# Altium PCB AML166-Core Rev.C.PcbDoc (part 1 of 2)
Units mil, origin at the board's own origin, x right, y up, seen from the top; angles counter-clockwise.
Board outline 3307.09 x 2047.24 mil, 4 copper layers (Top Layer, L2, L3, Bottom Layer), stack 30.634 mil thick; 138 components, 74 nets, 392 pads, 430 vias.
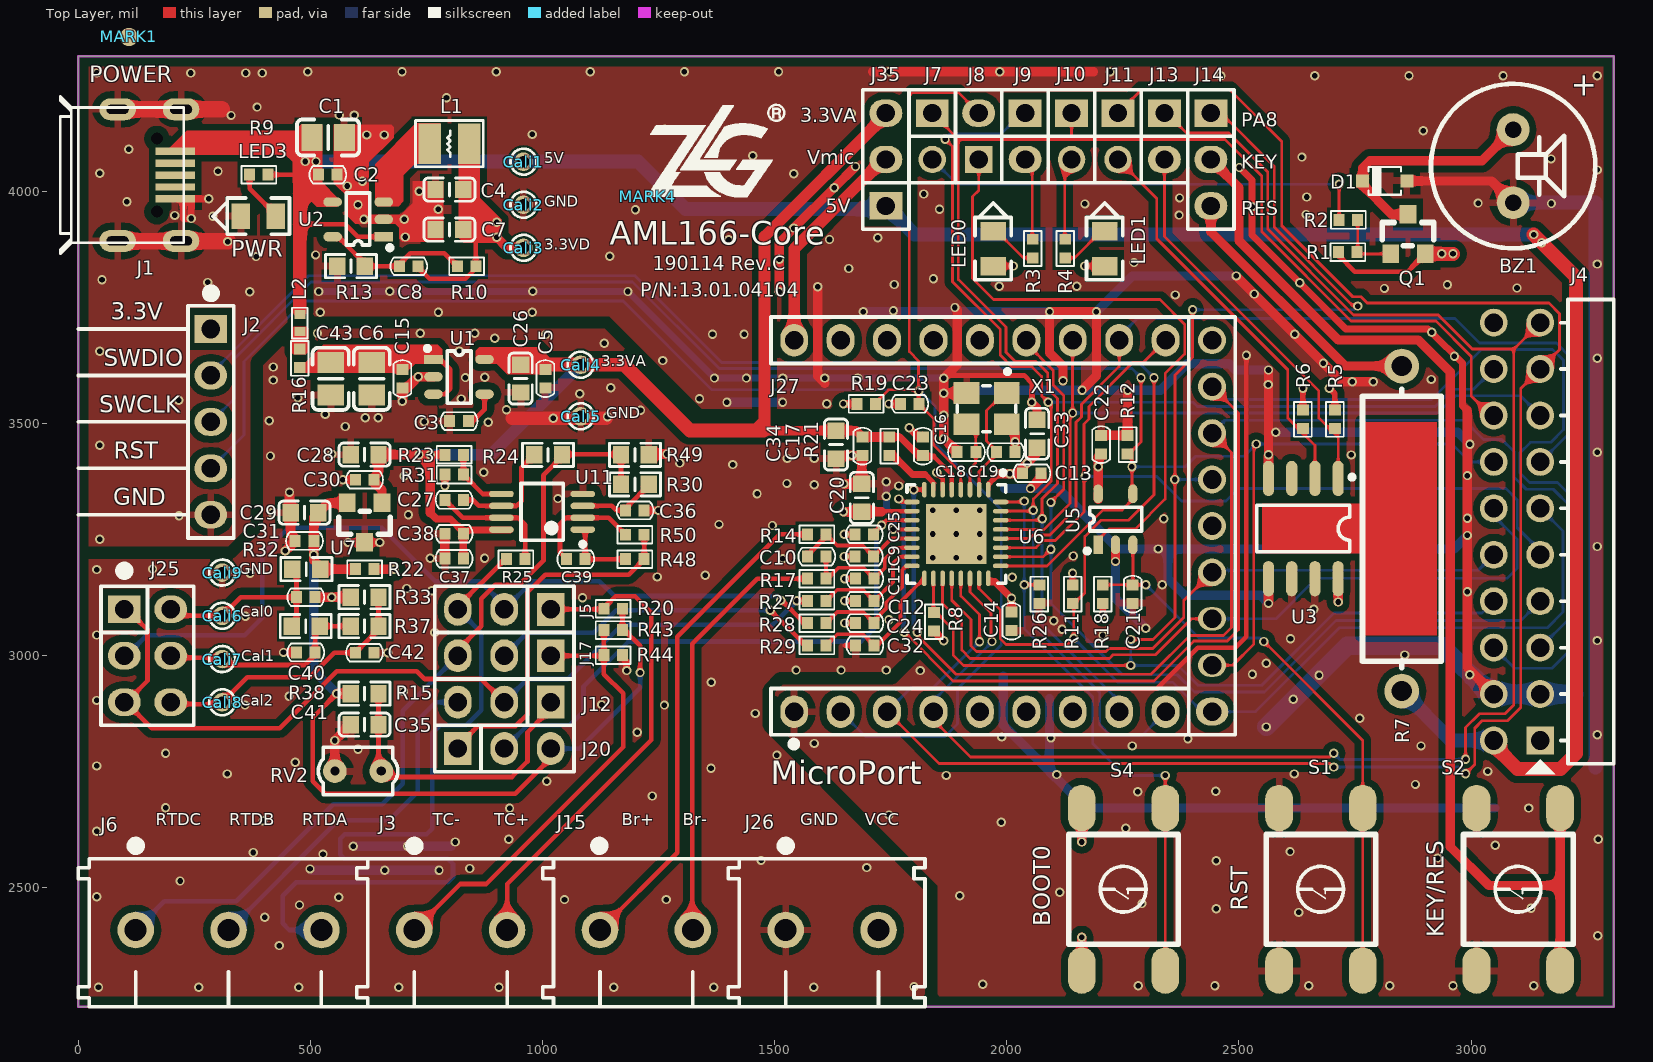
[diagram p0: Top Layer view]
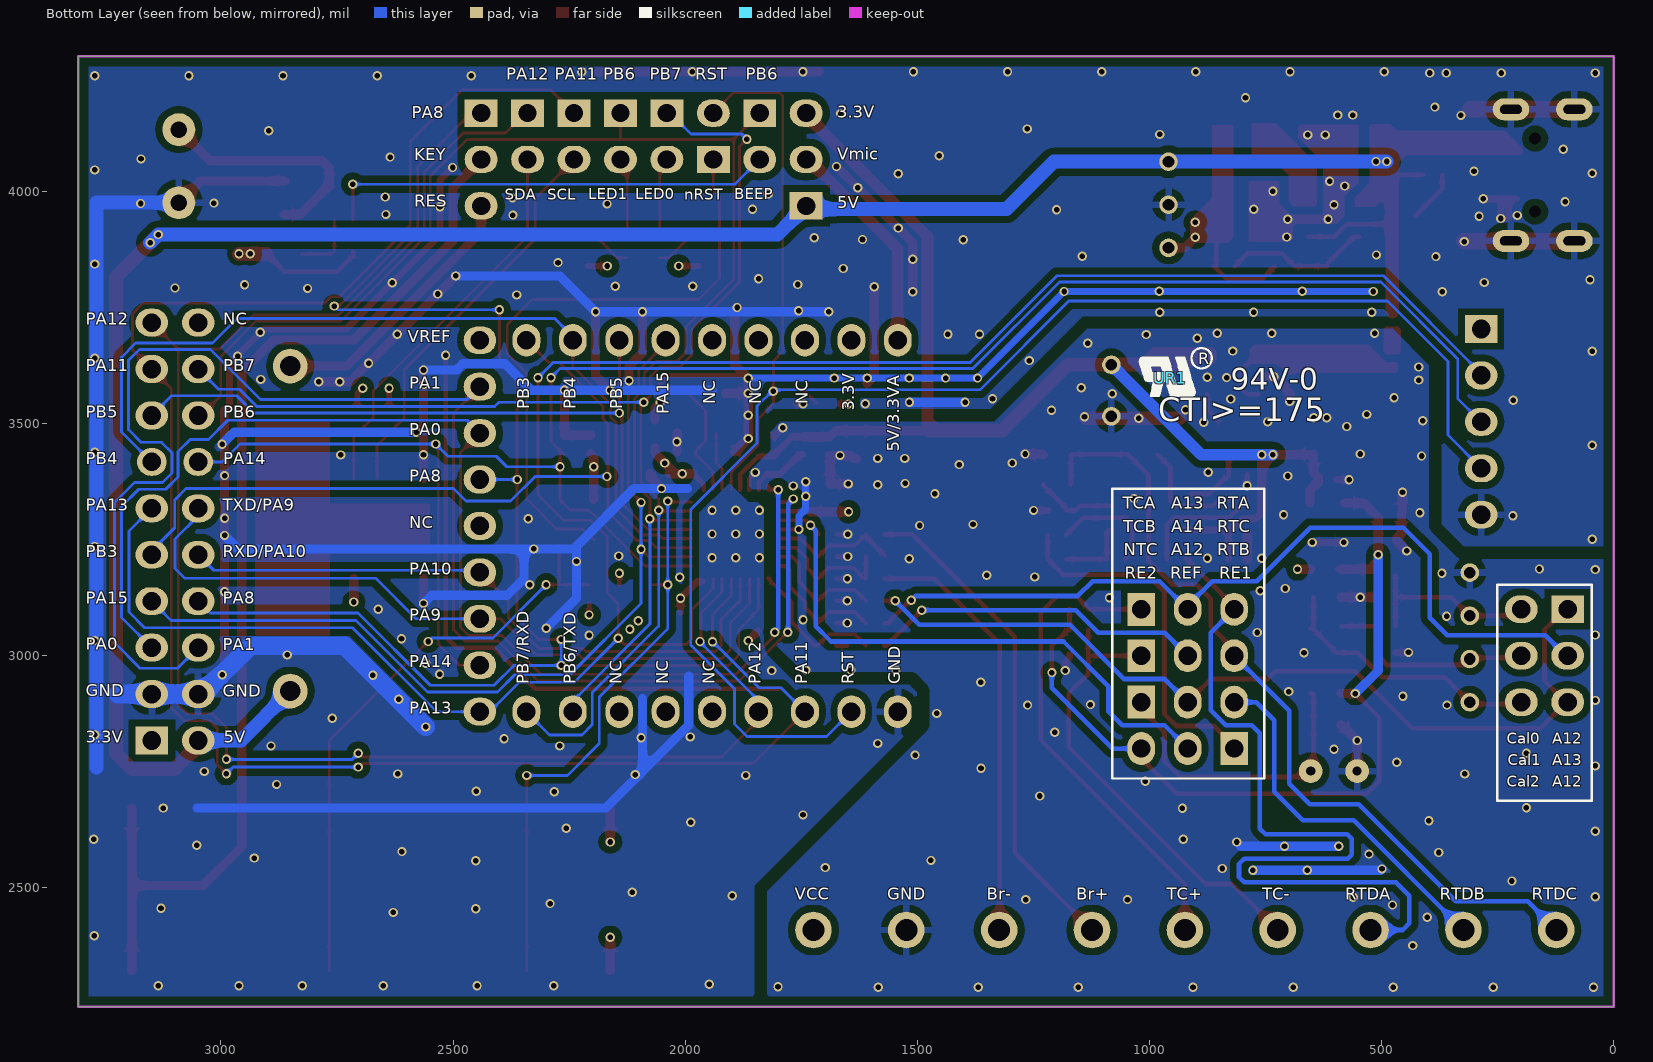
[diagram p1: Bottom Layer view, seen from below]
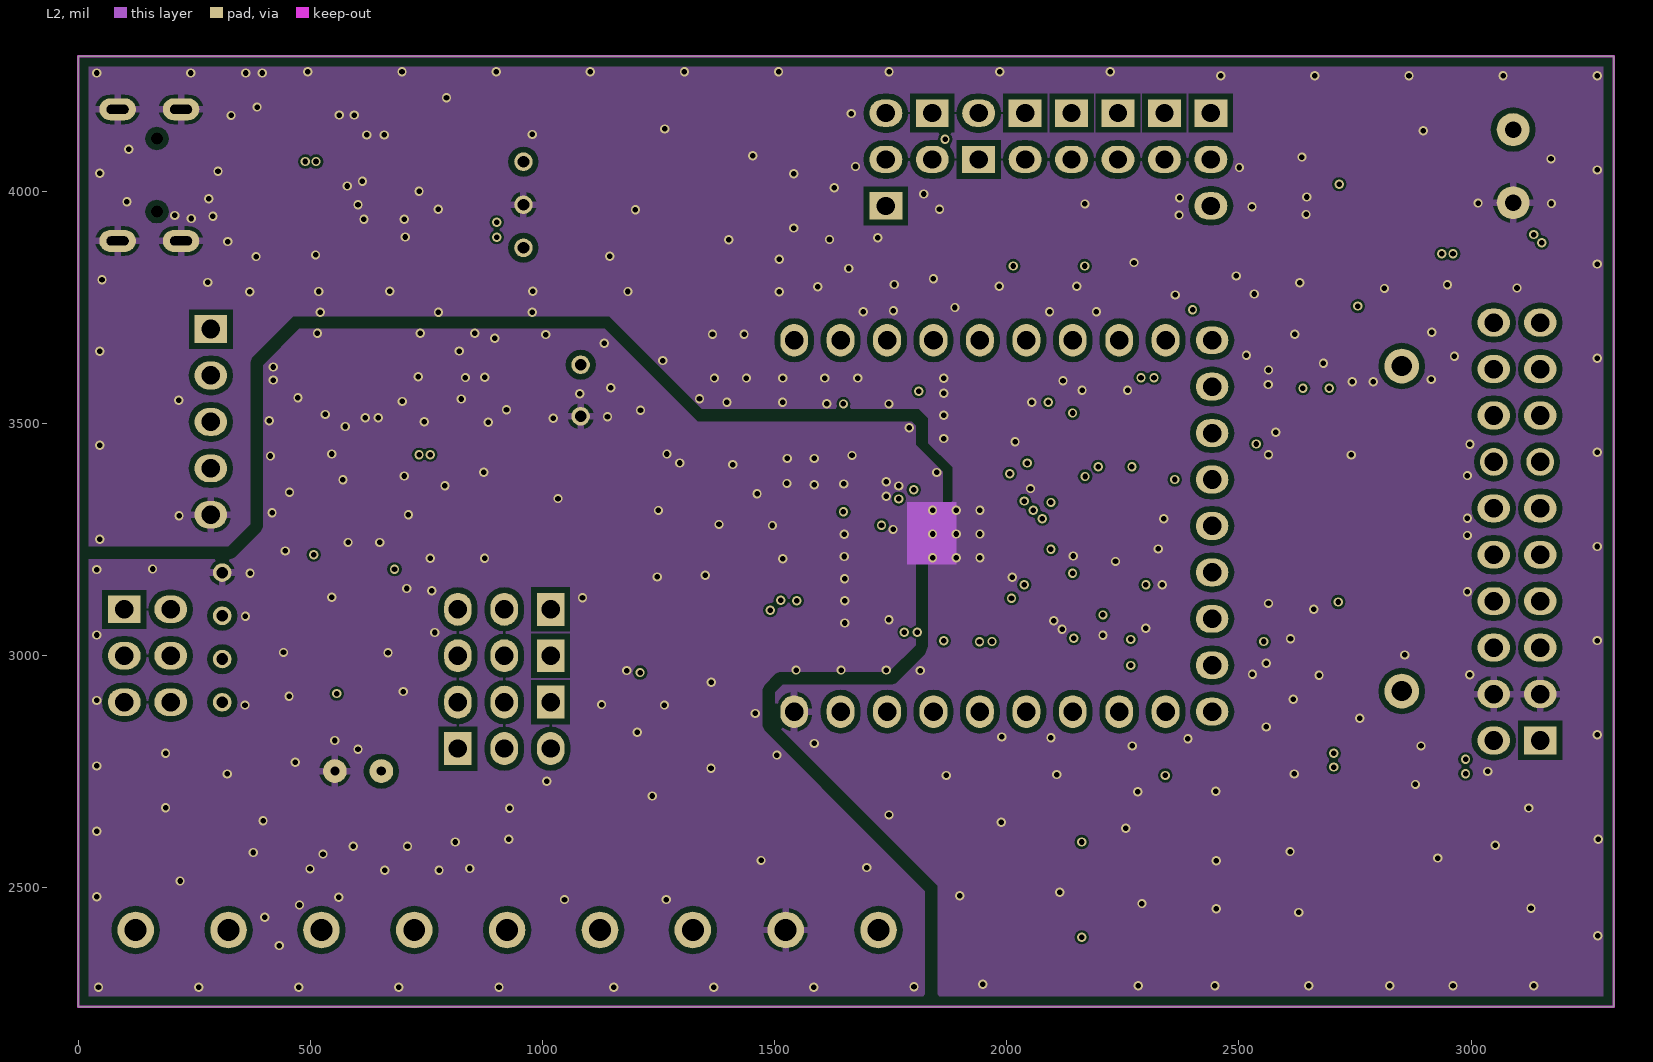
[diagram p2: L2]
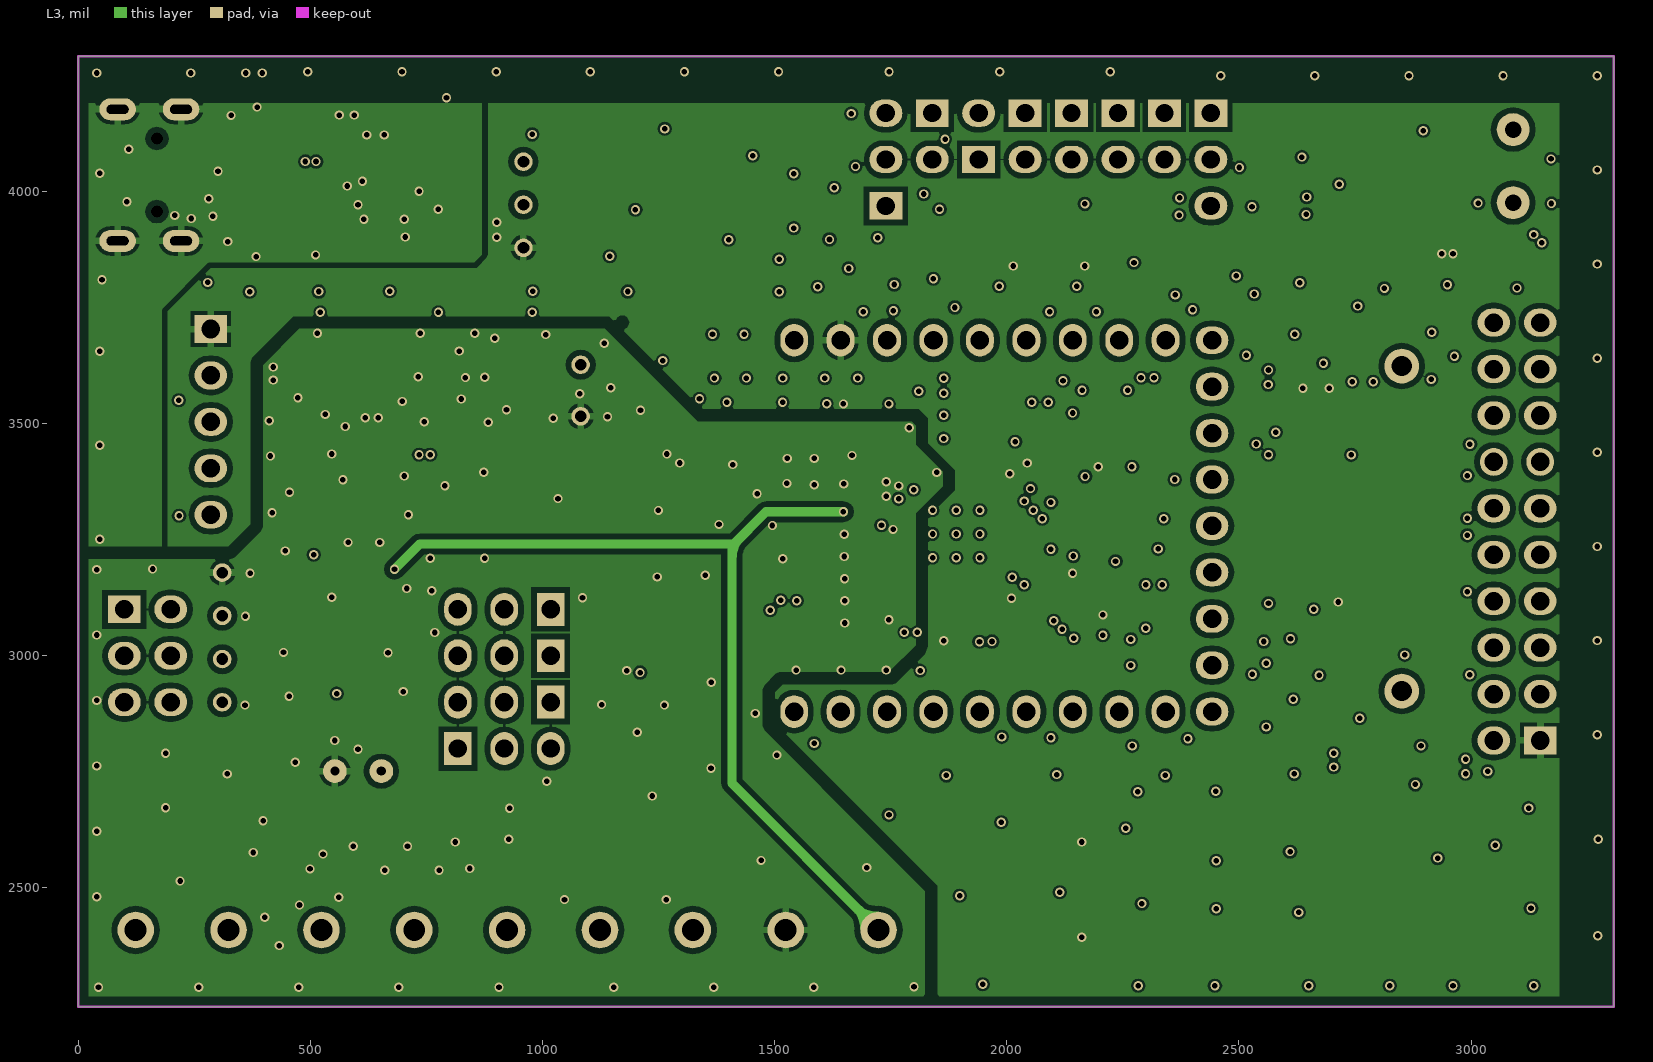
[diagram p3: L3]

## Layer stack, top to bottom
Top Layer: signal copper 1.4
Dielectric: core 10, FR-4, Dk 4.2
L2: signal copper 1.417
Dielectric: prepreg 5, Dk 4.2
L3: signal copper 1.417
Dielectric: core 10, Dk 4.2
Bottom Layer: signal copper 1.4

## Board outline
0,2244.09 3307.09,2244.09 3307.09,4291.34 0,4291.34

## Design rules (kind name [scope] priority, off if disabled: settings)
Clearance Clearance_Keepout [OnLayer('Keep-Out Layer')] p1: gap=20
Clearance Clearance_TP [HasFootprint('PAD-40') vs HasFootprint('PAD-40')] p2: gap=50
Clearance Clearance_Manual [OnLayer('Bottom Layer') and IsSMTPin vs IsPadHoleValid>  (  HasFootprint('PAD-35/50') or   HasFootprint('HOLE-3.2') or  HasFootprint('HOLE-3.2 - Screw') or   HasFootprint('HOLE4.22-SMT') or   HasFootprint('Mou Hole-300D450W310H-SMD') or  HasFootprint('AW6748') or  HasFootprint('IDCS80P500W-20X2-F')  )] p3: gap=50
Clearance Clearance_Via2Via [IsVia vs IsVia] p4: gap=6
Clearance Clearance_Surface [InLayerClass('Component Layers')] p5: gap=5
Clearance Clearance_Inner [inpoly] p6: gap=5
Clearance [All] p7: gap=6
DiffPairsRouting [All] p1: maxlimit=6 minlimit=6 mostfreqgap=6 maxuncoupledlength=500
HoleSize [All] p1: absolutevalues=TRUE maxlimit=1000 minlimit=1 maxpercent=80.000 minpercent=20.000
MinimumSolderMaskSliver [All] p1: minsoldermaskwidth=4
PlaneClearance PlaneClearance_Full [IsVia] p1: clearance=9
PlaneClearance [All] p2: clearance=22
PlaneConnect PlaneConnect_Full [IsVia] p1: planeconnectstyle=Direct reliefexpansion=20 reliefentries=4 reliefconductorwidth=10 reliefairgap=10
PlaneConnect [All] p2: planeconnectstyle=Relief reliefexpansion=16 reliefentries=4 reliefconductorwidth=15 reliefairgap=6
PolygonConnect PolygonConnect_SMDHole [HasFootprint('Mou Hole-300D450W310H-SMD') or HasFootprint('Mou Hole-373D600H-SMD')] p1: connectstyle=Relief reliefconductorwidth=80 reliefentries=4 polygonreliefangle="45 Angle"
PolygonConnect PolygonConnect_Full [IsVia or   HasFootprint('PAD-40') or   HasFootprint('PAD-35/50') or  HasFootprint('HOLE-3.2') or   HasFootprint('HOLE-3.2 - Screw')] p2: connectstyle=Direct reliefconductorwidth=10 reliefentries=4 polygonreliefangle="90 Angle"
PolygonConnect PolygonConnect_Surface [OnLayer('Top Layer')  or  OnLayer('Bottom Layer')] p3: connectstyle=Relief reliefconductorwidth=15 reliefentries=4 polygonreliefangle="90 Angle"
PolygonConnect PolygonConnect_Inner [All] p4: connectstyle=Relief reliefconductorwidth=15 reliefentries=4 polygonreliefangle="90 Angle"
RoutingVias [All] p1: holewidth=12 width=20 viastyle="Through Hole" minholewidth=12 minwidth=20 maxholewidth=12 maxwidth=20
SilkToSilkClearance [All] p1: silktosilkclearance=2
SilkscreenOverComponentPads SilkToSolderMaskClearance [IsPad] p1: minsilkscreentomaskgap=2
SolderMaskExpansion [All] p1: expansion=4
Width [All] p1: maxlimit=100 minlimit=5.5 preferedwidth=5.5
21 further rules are at their usual default settings.

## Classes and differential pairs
component class U_09: C21 C22 R18 S1 U5
component class U_08: C9 C10 C11 C12 C13 C14 C16 C17 C18 C19 C20 C23 C24 C25 C27 C28 C30 C31 C32 C33 C34 C35 C36 C37 C38 C39 C40 C41 C42 Cali6 Cali7 Cali8 Cali9 J2 J5 J8 J12 J17 J20 J25 R11 R12 R14 R15 R17 R19 R20 R21 R22 R23 R24 R25 R26 R27 R28 R29 R30 R31 R32 R33 R37 R38 R43 R44 R48 R49 R50 RV2 S4 U6 U7 U11 X1
component class U_07: J1
component class U_05: J4
component class U_04: J27 J35
component class U_03: BZ1 D1 J7 J9 J10 J11 J13 J14 LED0 LED1 Q1 R1 R2 R3 R4 R5 R6 R7 R8 S2 U3
component class U_02B: C1 C2 C3 C4 C5 C6 C7 C8 C15 C26 C43 Cali1 Cali2 Cali3 Cali4 Cali5 L1 L2 LED3 R9 R10 R13 R16 U1 U2
component class 01.mian: J3 J6 J15 J26 MARK1 MARK2 MARK3 MARK4 UR1

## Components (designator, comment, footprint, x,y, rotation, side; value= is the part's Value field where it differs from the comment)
BZ1 "BUZZER2" BUZZ-4/9 3090.55,4054.8 r270 top locked
C1 "10μF,10V" 0805C 538,4116.47 r0 top
C2 "0.1μF,±10%" 0402C 537.5,4036.37 r0 top
C3 "0.01μF,±10%" 0402C 820,3505.71 r180 top
C4 "10μF,6.3V" 0603C 799.31,4004.37 r180 top
C5 "0.1μF,±10%" 0402C 1006,3597.2 r270 top
C6 "10μF,10V" 0805C 632,3596.7 r270 top
C7 "10μF,6.3V" 0603C 799.31,3918.18 r180 top
C8 "18pF" 0402C 711.81,3839.18 r180 top
C9 "0.1μF" 0402C 1693.09,3213.93 r180 top
C10 "1μF,±10%" 0402C 1590.69,3213.93 r0 top
C11 "0.1μF" 0402C 1694.09,3166.18 r180 top
C12 "0.1μF" 0402C 1694.24,3118.43 r180 top
C13 "0.1μF" 0402C 2054,3393.34 r0 top
C14 "0.1μF" 0402C 2010,3074.49 r270 top
C15 "0.1μF,±10%" 0402C 698,3597.2 r270 top
C16 "0.1μF" 0402C 1819.03,3451.65 r90 top
C17 "0.1μF" 0402C 1689,3451.65 r270 top
C18 "12pF,±5%" 0402C 1913.09,3438.92 r0 top
C19 "12pF,±5%" 0402C 1997.73,3438.92 r0 top
C20 "10μF" 0603C 1687.49,3340.3 r90 top
C21 "0.1μF,±10%" 0402C 2271,3133.02 r270 top
C22 "0.1μF,±10%" 0402C 2203.09,3455.02 r270 top
C23 "0.1μF,±10%" 0402C 1791,3542.53 r180 top
C24 "0.1μF" 0402C 1694.24,3070.68 r180 top
C25 "1μF" 0402C 1693.09,3261.68 r0 top
C26 "10μF,6.3V" 0603C 952.59,3597.2 r270 top
C27 "22pF,±5%" 0402C 809.37,3335.91 r180 top
C28 "10μF" 0603C 616.57,3433.39 r0 top
C29 "10μF,6.3V" 0603C 487.16,3308.46 r0 top
C30 "0.1μF" 0402C 616.57,3379.39 r180 top
C31 "0.1μF" 0402C 487.16,3247.37 r180 top
C32 "0.1μF" 0402C 1694.24,3022.34 r180 top
C33 "10μF,6.3V" 0603C 2065.09,3478.34 r270 top
C34 "10μF,6.3V" 0603C 1632,3455 r90 top
C35 "10μF" 0603C 616.57,2851.71 r0 top
C36 "1μF,±10%" 0402C 1198.94,3313.27 r0 top
C37 "4.7μF" 0402C 809.37,3209.27 r180 top
C38 "0.1μF" 0402C 809.37,3263.08 r180 top
C39 "0.01μF,±10%" 0402C 1071.76,3208.27 r0 top
C40 "1μF,±10%" 0402C 490,3126.37 r180 top
C41 "1μF,±10%" 0402C 490,3007.37 r0 top
C42 "1μF,±10%" 0402C 616.57,3006.73 r180 top
C43 "10μF,10V" 0805C 543.62,3596.7 r270 top
Cali1 "5V" PAD-25/40 958.81,4064.37 r90 top
Cali2 "GND" PAD-25/40 958.81,3971.59 r90 top
Cali3 "3.3V" PAD-25/40 958.81,3878.81 r0 top
Cali4 "5V" PAD-25/40 1082,3627 r90 top
Cali5 "GND" PAD-25/40 1082,3516 r90 top
Cali6 "TEST1" PAD-25/40 309.87,3086.23 r180 top
Cali7 "TEST2" PAD-25/40 309.87,2993.11 r180 top
Cali8 "TEST3" PAD-25/40 309.87,2900 r180 top
Cali9 "TEST0" PAD-25/40 309.87,3179.34 r180 top
D1 "DIODE1" SOD-323 2814.09,4022.84 r180 top
J1 "A01SB141B1-261,MicroUSB插座" MICROUSB-5S 0,4035.43 r270 top locked
J2 "SWDIO" SIP-5-2.54-6.0-R90 285.43,3503.94 r270 top locked
J3 "Value" CON508P810W130D15S-2DIP 823.62,2403.54 r0 top locked
J4 "HEADER 10X2" IDC-20-2.54-R90 3098.82,3267.72 r90 top locked
J5 "CON3" SIP-3-2.54 917.52,3100.24 r180 top
J6 "DG127-5.08" CON508P1524L810W110D15S-3DIP 323.62,2403.54 r0 top locked
J7 "BEEP" SIP-2-2.54#1 1839.37,4119.09 r270 top locked
J8 "nRST" SIP-2-2.54#2 1939.37,4119.09 r90 top locked
J9 "LED0" SIP-2-2.54#3 2039.37,4119.09 r270 top locked
J10 "LED1" SIP-2-2.54#1 2139.37,4119.09 r270 top locked
J11 "SCL" SIP-2-2.54#1 2239.37,4119.09 r270 top locked
J12 "CON3" SIP-3-2.54 917.52,2900.24 r180 top locked
J13 "SDA" SIP-2-2.54#3 2339.37,4119.09 r270 top locked
J14 "KEY" SIP-3-2.54 2439.37,4069.09 r270 top locked
J15 "Value" CON508P810W130D15S-2DIP 1223.62,2403.54 r0 top locked
J17 "CON3" SIP-3-2.54 917.52,3000.24 r180 top
J20 "CON3" SIP-3-2.54 917.52,2800.24 r0 top locked
J25 "HEADER 3X2" IDC-6-2.54 149,3000.24 r270 top
J26 "Value" CON508P810W130D15S-2DIP 1623.62,2403.54 r0 top locked
J27 "3X7Inter" "SIP-27 2.54C" 1991.98,3279.79 r90 top locked
J35 "Vol_Sel" SIP-3-2.54 1739.37,4069.09 r90 top locked
L1 "MPH252012C2R2MT,2.2μH" INDC2520X10N 799.31,4103.37 r0 top
L2 "BM02Y190S40R" 0402RL 477,3716.89 r90 top
LED0 "LED1" LED-0805 1970.63,3877.29 r90 top
LED1 "LED1" LED-0805 2210.71,3877.29 r90 top
LED3 "LED1" LED-0805 388,3947 r180 top
MARK1 "MARKER" MARKER-C-1.0M 109,4333 r90 top
MARK2 "MARKER" MARKER-C-1.0M 105,155 r90 top
MARK3 "MARKER" MARKER-C-1.0M 6467,156 r90 top
MARK4 "ZLG" ZLG0.7 1226.51,3989.09 r0 top
Q1 "PNP-1" SOT-23 2864.09,3908.34 r90 top
R1 "RTT02103JTH,10K" 0402R 2734.5,3869.82 r180 top
R2 "1.5K,±1%" 0402R 2735.69,3938.82 r0 top
R3 "1.5K,±1%" 0402R 2055.71,3877.29 r90 top
R4 "1.5K,±1%" 0402R 2125.71,3877.29 r90 top
R5 "RTT02103JTH,10K" 0402R 2706.72,3509.34 r90 top
R6 "RTT02103JTH,10K" 0402R 2637.72,3509.34 r90 top
R7 "20Ω,±5%" RESAD1778W80L1450D430P 2850.63,3274.09 r90 top locked
R8 "RTT02472JTH,4.7K" 0402R 1843,3073.37 r90 top
R9 "1.5K,±1%" 0402R 389,4036.37 r0 top
R10 "680K,1%" 0402R 836.31,3839.18 r0 top
R11 "RTT02103JTH,10K" 0402R 2142,3133.02 r90 top
R12 "RTT02103JTH,10K" 0402R 2260,3455.02 r270 top
R13 "150KΩ" 0603R 587.31,3839.18 r0 top
R14 "100Ω,±1%" 0402R 1590.69,3261.68 r0 top
R15 "10KΩ,1/16W" 0603R 616.57,2918.71 r0 top
R16 "10Ω,±0.5%" 0402R 477,3640.62 r270 top
R17 "100Ω,±1%" 0402R 1590.69,3166.18 r0 top
R18 "RTT02103JTH,10K" 0402R 2206.5,3133.02 r90 top
R19 "RTT02103JTH,10K" 0402R 1697,3542.53 r0 top
R20 "10M,±5%" 0402R 1152,3101.49 r0 top
R21 "RTT02000JTH,0Ω" 0402R 1746.7,3451.65 r270 top
R22 "RTT02000JTH,0Ω" 0402R 616.57,3186.71 r0 top
R23 "12K,±5%" 0402R 809.37,3432.96 r0 top
R24 "4.7KΩ" 0603R 1011.85,3432.96 r180 top
R25 "100Ω,±1%" 0402R 942.35,3208.27 r180 top
R26 "RTT02103JTH,10K" 0402R 2070,3133.02 r270 top
R27 "100Ω,±1%" 0402R 1590.69,3118.43 r0 top
R28 "100Ω,±1%" 0402R 1590.69,3070.39 r0 top
R29 "100Ω,±1%" 0402R 1590.69,3022.34 r0 top
R30 "47KΩ" 0603R 1198.94,3369.27 r0 top
R31 "20KΩ,±0.5%" 0402R 809.37,3390.44 r0 top
R32 "20KΩ,1/16W" 0603R 491.16,3186.71 r0 top
R33 "20KΩ,1/16W" 0603R 616.57,3126.37 r180 top
R37 "499Ω" 0603R 616.57,3064 r180 top
R38 "51Ω,10ppm" 0603R 490,3064 r0 top
R43 "1K,±1%" 0402R 1152,3055.49 r0 top
R44 "1K,±1%" 0402R 1152,3001.49 r0 top
R48 "200Ω,±1%" 0402R 1198.94,3208.27 r0 top
R49 "2KΩ" 0603R 1198.94,3432.96 r180 top
R50 "100Ω,±0.5%" 0402R 1198.94,3260.77 r180 top
RV2 "103AP2" RESRR254W35L380T260H850P 602.57,2751.71 r0 top
S1 "TS0641-0501B,6×6×5.0mm" KEY-6S 2676.52,2497.09 r90 top
S2 "SW-PB4P" KEY-6S 3101.69,2497.09 r90 top
S4 "SW-PB4P" KEY-6S 2251.34,2497.09 r90 top
U1 "CAT6219-330TD" SOT-23-5 820,3601.07 r0 top
U2 "NCP1529ASNT1G" SOT-23-5 602.81,3940.18 r180 top
U3 "LM75B" SOIC127P600X175-8N 2638.63,3274.09 r270 top locked
U5 "CAT823STDI-GT3" SOT-23-5 2234.09,3294.02 r90 top
U6 "ZML166" QFN50P500X500X85-33N 1891.09,3262.51 r270 top
U7 "REF3325AIDBZR" SOT-23 616.57,3286.8 r270 top
U11 "TP5592-VR" SOP65P490X120-8N 998.94,3310.27 r180 top
UR1 "UR" ZY_UR-3X2 955.48,3597.98 r180 bottom
X1 "JYD3A1C7G5-12.5-16.000,16.0000MHz" OSCCC250X320X80-4N 1956.39,3532.24 r180 top

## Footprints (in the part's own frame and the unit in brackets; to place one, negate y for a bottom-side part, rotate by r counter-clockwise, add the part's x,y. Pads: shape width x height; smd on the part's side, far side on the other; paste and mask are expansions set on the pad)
0402C [mm]
  rect 0.6x0.65 smd mask+0.025: 1(-0.508,0) 2(0.508,0)
  silkscreen extent -1.01,-0.48 1.01,0.48, body extent -0.51,-0.23 0.49,0.27, height 0.5
0402R [mm]
  rect 0.6x0.65 smd mask+0.025: 1(-0.508,0) 2(0.508,0)
  silkscreen extent -0.95,-0.48 0.95,0.48, body extent -0.47,-0.25 0.53,0.25, height 0.35
0402RL [mm]
  rect 0.5x0.6 smd mask+0.051: 1(-0.458,0) 2(0.458,0)
  silkscreen extent -0.84,-0.43 0.84,0.43, body extent -0.52,-0.25 0.48,0.25, height 0.35
0603C [mm]
  rect 0.9x0.95 smd: 1(-0.762,0) 2(0.762,0)
  silkscreen extent -1.4,-0.64 1.4,0.64, body extent -0.79,-0.38 0.81,0.42, height 0.3
0603R [mm]
  rect 0.9x0.95 smd: 1(-0.762,0) 2(0.762,0)
  silkscreen extent -1.4,-0.64 1.4,0.64, body extent -0.8,-0.4 0.8,0.4, height 0.3
0805C [mm]
  rect 1.15x1.45 smd: 1(-0.889,0) 2(0.889,0)
  silkscreen extent -1.7,-0.99 1.7,0.99, body extent -1,-0.63 1,0.63, height 0.78
BUZZ-4/9 [mm]
  round 1.8 hole 0.9: 1(-2,0) 2(2,0)
  silkscreen extent -4.5,-4.5 4.5,4.5
CON508P810W130D15S-2DIP [mm]
  round 2 hole 1.2: 1(-2.54,0.15) 2(2.54,0.15)
  silkscreen extent -5.68,-4.05 5.08,5
CON508P1524L810W110D15S-3DIP [mm]
  round 2 hole 1.2: 1(-5.08,0.15) 2(0,0.15) 3(5.08,0.15)
  silkscreen extent -8.22,-4.05 7.62,5
IDC-6-2.54 [mm]
  rect 1.5x1.8 hole 1: 1(-2.54,-1.27)
  oval 1.5x1.8 hole 1: 2(-2.54,1.27) 3(0,-1.27) 4(0,1.27) 5(2.54,-1.27) 6(2.54,1.27)
  silkscreen extent -4.9,-2.54 3.81,2.54, body extent -3.81,-2.54 3.81,2.54, height 7.58
IDC-20-2.54-R90 [mil]
  rect 60x60 / inner rect 60x70 / far side rect 60x70 hole 40: 1(-450,-50)
  round 60 / inner oval 60x70 / far side oval 60x70 hole 40: 2(-450,50) 3(-350,-50) 4(-350,50) 5(-250,-50) 6(-250,50) 7(-150,-50) 8(-150,50) 9(-50,-50) 10(-50,50) 11(50,-50) 12(50,50) 15(250,-50) 16(250,50) 17(350,-50) 18(350,50) 19(450,-50) 20(450,50)
  round 60 / inner round 60 / far side oval 60x64 hole 40: 13(150,-50) 14(150,50)
  silkscreen extent -522,-208 500,-17
INDC2520X10N [mm] "Chip Inductor, 2-Leads, Body 2.50x2.00mm, IPC Medium Density"
  rect 1.23x2.22 smd: 1(-1.085,0) 2(1.085,0)
  Top Layer pour cut-out: -0.457,-1.118 -0.457,1.118 0.457,1.118 0.457,-1.118
  silkscreen extent -1.85,-1.27 1.85,1.27, body extent -1.35,-1.1 1.35,1.1, height 1
KEY-6S [mil]
  oval 100x60 smd: 1(-175,90) 2(-175,-90) 3(175,-90) 4(175,90)
  silkscreen extent -118,-118 118,118, body extent -201,-122 201,122, height 268
LED-0805 [mm] "170907内距改0.9mm"
  rect 1.014x1.4 smd: 1(-0.957,0) 2(0.957,0)
  silkscreen extent -1.7,-0.99 2.49,0.99, body extent -1,-0.64 1,0.64, height 1.1
MARKER-C-1.0M [mm]
  round 1 smd paste-1.016 mask+0.5: 0(0,0)
  Top Layer pour cut-out: -1.1,0 -1.016,-0.421 -0.778,-0.778 -0.421,-1.016 0,-1.1 0,-1.1 0.421,-1.016 0.778,-0.778 1.016,-0.421 1.1,0 1.1,0 1.016,0.421 0.778,0.778 0.421,1.016 0,1.1 0,1.1 -0.421,1.016 -0.778,0.778 -1.016,0.421 -1.1,0
MICROUSB-5S [mm]
  oval 1.2x2 on Top Paste: 0(-3.6,2.15) 0(-3.6,5.62) 0(3.6,2.15) 0(3.6,5.62)
  round 0.54 hole 0.65 unplated: 0(-2,4.3) 0(2,4.3)
  rect 0.4x2.15 smd: 1(-1.3,5.31) 2(-0.65,5.31) 3(0,5.31) 4(0.65,5.31) 5(1.3,5.31)
  oval 1.2x2 hole 0.5 slot 1.2 at 90 deg: 6(-3.6,5.62) 7(3.6,5.62) 8(-3.6,2.15) 9(3.6,2.15)
  silkscreen extent -4.3,-0.99 4.3,5.77
OSCCC250X320X80-4N [mm]
  rect 1.4x1.2 smd: 1(-1.1,-0.85) 2(1.1,-0.85) 3(1.1,0.85) 4(-1.1,0.85)
  silkscreen extent -1.6,-2.16 1.6,1.25
PAD-25/40 [mil]
  round 40 hole 25: 1(0,0)
  silkscreen extent -28,-28 28,28
QFN50P500X500X85-33N [mm] "QFN, 32-Leads, Body 5.00x5.00mm, Pitch 0.50mm, Thermal Pad 3.60x3.60mm, IPC Medium Density"
  oval 0.85x0.25 smd: 1(-2.425,1.75) 2(-2.425,1.25) 3(-2.425,0.75) 4(-2.425,0.25) 5(-2.425,-0.25) 6(-2.425,-0.75) 7(-2.425,-1.25) 8(-2.425,-1.75) 17(2.425,-1.75) 18(2.425,-1.25) 19(2.425,-0.75) 20(2.425,-0.25) 21(2.425,0.25) 22(2.425,0.75) 23(2.425,1.25) 24(2.425,1.75)
  oval 0.25x0.85 smd: 9(-1.75,-2.425) 10(-1.25,-2.425) 11(-0.75,-2.425) 12(-0.25,-2.425) 13(0.25,-2.425) 14(0.75,-2.425) 15(1.25,-2.425) 16(1.75,-2.425) 25(1.75,2.425) 26(1.25,2.425) 27(0.75,2.425) 28(0.25,2.425) 29(-0.25,2.425) 30(-0.75,2.425) 31(-1.25,2.425) 32(-1.75,2.425)
  rect 3.3x3.3 smd: 33(0,0)
  silkscreen extent -3.47,-2.7 2.7,2.7, body extent -2.55,-2.55 2.55,2.55, height 0.85
RESAD1778W80L1450D430P [mm]
  round 1.9 hole 1.1: 1(-8.89,0) 2(8.89,0)
  silkscreen extent -7.62,-2.15 7.62,2.15
RESRR254W35L380T260H850P [mm]
  round 1.3 hole 0.5: 1(-1.27,0) 2(1.27,0)
  silkscreen extent -2.18,-1.3 2.18,1.3
SIP-2-2.54#1 [mm]
  rect 1.5x1.8 hole 1: 1(-1.27,0)
  round 1.5 / inner oval 1.5x1.8 / far side oval 1.5x1.8 hole 1: 2(1.27,0)
  silkscreen extent -2.54,-1.27 2.54,1.27, body extent -2.54,-1.27 2.54,1.27, height 7.58
SIP-2-2.54#2 [mm]
  rect 1.5x1.5 / inner rect 1.5x1.8 / far side rect 1.5x1.8 hole 1: 1(-1.27,0)
  oval 1.5x1.8 hole 1: 2(1.27,0)
  silkscreen extent -2.54,-1.27 2.54,1.27, body extent -2.54,-1.27 2.54,1.27, height 7.58
SIP-2-2.54#3 [mm]
  rect 1.5x1.8 hole 1: 1(-1.27,0)
  oval 1.5x1.8 hole 1: 2(1.27,0)
  silkscreen extent -2.54,-1.27 2.54,1.27, body extent -2.54,-1.27 2.54,1.27, height 7.58
SIP-3-2.54 [mm]
  rect 1.5x1.8 hole 1: 1(-2.54,0)
  oval 1.5x1.8 hole 1: 2(0,0) 3(2.54,0)
  silkscreen extent -3.81,-1.27 3.81,1.27, body extent -3.81,-1.27 3.81,1.27, height 7.58
SIP-5-2.54-6.0-R90 [mil] "引脚伸出部分为6.0mm"
  rect 60x70 hole 40: 1(-200,0)
  oval 60x70 hole 40: 2(-100,0) 3(0,0) 4(100,0) 5(200,0)
  silkscreen extent -286,-285 250,49
"SIP-27 2.54C" [mil]
  oval 70x60 hole 40: 1(-400,450) 2(-400,350) 3(-400,250) 4(-400,150) 5(-400,50) 6(-400,-50) 7(-400,-150) 8(-400,-250) 9(-400,-350) 19(400,-350) 20(400,-250) 21(400,-150) 22(400,-50) 23(400,50) 24(400,150) 25(400,250) 26(400,350) 27(400,450)
  oval 60x70 hole 40: 10(-400,-450)
  oval 50x60 / inner oval 60x70 / far side oval 60x70 hole 40: 11(-300,-450) 12(-200,-450)
  round 60 / inner oval 60x70 / far side oval 60x70 hole 40: 13(-100,-450) 14(0,-450) 15(100,-450) 16(200,-450) 17(300,-450) 18(400,-450)
  silkscreen extent -476,-500 450,500
SOD-323 [mil]
  rect 28x28 smd: 1(-47.5,0) 2(47.5,0)
  silkscreen extent -35,-30 35,30, body extent -51,-26 51,25, height 39
SOIC127P600X175-8N [mil]
  oval 76.06x24 smd: 1(-108.03,75) 2(-108.03,25) 3(-108.03,-25) 4(-108.03,-75) 5(108.03,-75) 6(108.03,-25) 7(108.03,25) 8(108.03,75)
  silkscreen extent -116,-100 50,110, body extent -118,-96 118,97, height 61
SOP65P490X120-8N [mm] "TSOP, 8-Leads, Body 3.00x3.00mm, Pitch 0.65mm, IPC Medium Density"
  oval 1.35x0.35 smd: 1(-2.225,0.975) 2(-2.225,0.325) 3(-2.225,-0.325) 4(-2.225,-0.975) 5(2.225,-0.975) 6(2.225,-0.325) 7(2.225,0.325) 8(2.225,0.975)
  silkscreen extent -2.35,-1.55 1.15,1.9, body extent -1.55,-1.55 1.55,1.55, height 1.2
SOT-23 [mil]
  rect 40x36 smd: 1(-42.5,37.4) 2(-42.5,-37.4) 3(42.5,0)
  silkscreen extent -25,-56 25,56, body extent -47,-57 50,58, height 39
SOT-23-5 [mil]
  rect 40x20 smd: 1(-55,37.4)
  oval 40x20 smd: 2(-55,0) 3(-55,-37.4) 4(55,-37.4) 5(55,37.4)
  silkscreen extent -73,-57 26,66, body extent -55,-57 55,57, height 43
ZLG0.7 [mil] "7.8mmX5.6mm     不是太标准"
  silkscreen extent -2,0 294,198
ZY_UR-3X2 [mil]
  silkscreen extent -67,-40 90,65

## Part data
BZ1: library part 1.06.09.0016, "Buzzer有极性"
C1 C6 C43: library part 1.02.02.0117, "10μF,±10%,10V,X7R,GRM21BR71A106KE51L,0805,muRata,RoHS"
C2 C5 C15 C21 C22 C23: library part 1.02.17.0006, "GRM155R71C104KA88D,0.1μF,±10%,16V,X7R,0402,muRata,RoHS"
C3 C39: library part 1.02.17.0019, "GRM155R71H103KA88D,0.01μF,±10%,50V,X7R,0402,muRata,RoHS"
C4 C7 C20 C26 C28 C29 C33 C34 C35: library part 1.02.01.0065, "10μF,6.3V,X5R,GRM188R60J106M****,0603,Murata,RoHS"
C8: library part 1.02.17.0078, "GRM1555C1H180JA01D,18pF,±5%,50V,C0G,0402,muRata,RoHS"
C9 C11 C12 C13 C14 C16 C17 C24 C30 C31 C32 C38: library part 1.02.17.0118, "GCM155R71E104KE02D,0.1μF,±10%,25V,X7R,0402,muRata,RoHS"
C10 C25 C36 C40 C41 C42: library part 1.02.17.0092, "GRM155R61C105KA12D,1μF,±10% ,16V,X5R,0402,muRata,RoHS"
C18 C19: library part 1.02.17.0018, "GRM1555C1H120JA01D,12pF,±5%,50V,C0G,0402,muRata,RoHS"
C27: library part 1.02.17.0036, "GRM1555C1H220JA01D,22pF,±5%,50V,C0G,0402,muRata,RoHS"
C37: library part 1.02.17.0073, "GRM155R60J475ME87D,4.7μF,±20%,6.3V,X5R,0402,muRata,RoHS"
Cali1 Cali2 Cali3 Cali4 Cali5 Cali6 Cali7 Cali8 Cali9: library part TEST-DOT
D1: library part 1.04.07.0027, "1N4148,SOD-323,RoHS"
J1: library part 1.10.12.0014, "A01SB141B1-261,MicroUSB插座,SMT,艾立信,RoHS"
J2: library part CON5, "Connector"
J3 J15 J26: library part 1.10.06.0070, "DG127-5.08-02P-14-00AH,180°,绿色,DEGSON,RoHS"
J5 J12 J17 J20: "Connector"
J6: library part 19.04.00251, "DG127-5.08-03P-14-00AH,180°,绿色,THT"
J7 J8 J9 J10 J11 J13: library part CON2, "Connector"
J14 J35: library part CON3, "Connector"
L1: library part 1.03.01.0347, "MPH252012C2R2MT,2.2μH,±20%,700mA,1008,Sunlord,RoHs"
L2: library part 1.03.03.0022, "BM02Y190S40R,0402,丰晶,RoHS"
LED0 LED1: library part 1.04.05.0002, "绿色,0805,0805,RoHS"
LED3: library part 1.04.05.0001, "红色,0805,0805,RoHS"
Q1: library part 1.04.09.0002, "PNP Transistor"
R1 R5 R6 R11 R12 R18 R19 R26: library part 1.01.17.0006, "RTT02103JTH,10K,±5%,0402,RALEC,RoHS"
R2 R3 R4 R9: library part 1.01.17.0011, "1.5K,±1%,0402,RALEC,RoHS"
R7: library part 1.01.10.0003, "20Ω,±5%,2W,Ф5.5×16mm,RoHS"
R8: library part 1.01.17.0019, "RTT02472JTH,4.7K,±5%,0402,RALEC,RoHS"
R10: library part 1.01.17.0086, "680K,1%,0402,Ralec,RoHS"
R13: library part 1.01.01.0065, "150KΩ,0603,*,RoHS"
R14 R17 R25 R27 R28 R29: library part 1.01.17.0029, "100Ω,±1%,0402,RALEC,RoHS"
R15: library part 1.01.01.0192, "10KΩ,1/16W,10PPM/℃,±0.1%,0603,Viking,RoHS"
R16: library part 1.01.17.0049, "10Ω,±0.5%,0402,RoHS"
R20: library part 1.01.17.0005, "10M,±5%,0402,RALEC,RoHS"
R21 R22: library part 1.01.17.0004, "RTT02000JTH,0Ω,±5%,0402,RALEC,RoHS"
R23: library part 1.01.17.0035, "12K,±5%,0402,RALEC,RoHS"
R24: library part 1.01.01.0045, "4.7KΩ,0603,*,RoHS"
R30: library part 1.01.01.0060, "47KΩ,0603,*,RoHS"
R31: library part 1.01.17.0053, "20KΩ,±0.5%,0402,RoHS"
R32 R33: library part 1.01.01.0207, "20KΩ,1/16W,10PPM/℃,±0.1%,0603,Viking,RoHS"
R37: library part 1.01.01.0155, "499Ω,RN731JTTD,4990B10,0603,KOA,RoHS"
R38: library part 1.01.01.0215, "51Ω,10ppm,±0.1%,AR03BTB0510,0603,Viking,RoHS"
R43 R44: library part 1.01.17.0016, "1K,±1%,0402,RALEC,RoHS"
R48: library part 1.01.17.0073, "200Ω,±1%,0402,RoHS"
R49: library part 1.01.01.0157, "2KΩ,RN731JTTD,2001B10,0603,KOA,RoHS"
R50: library part 1.01.17.0052, "100Ω,±0.5%,0402,RoHS"
RV2: library part 1.01.14.0020, "103AP2,SIP,semitec,RoHS"
S1: library part 1.09.01.0003, "TS0641-0501B,6×6×5.0mm,黑色,SMD,卷带装,RoHS"
S2 S4: library part 1.09.01.0003, "6×6×5.0mm,黑色,SMD,,*"
U1: library part 1.05.10.0321, "CAT6219-330TD,TSOT-23-5,ON,RoHS"
U2: library part 1.05.09.0091, "NCP1529ASNT1G,TSOP-5,ON,RoHS"
U3: library part 1.05.10.0602, "LM75BD,SO-9,NXP,RoHS"
U5: library part CAT823, "1.05.07.0025"
U7: library part 1.05.10.0334, "REF3325AIDBZR,SOT-23,TI"
U11: library part 1.05.20.0102, "TP5592-VR,MSOP-8,3PEAK,RoHS"
X1: library part 1.07.03.0077, "JYD3A1C7G5-12.5-16.000,16.0000MHz,±10ppm,12.5pF,-40~85℃,SMD3225,JYEG,RoHS"

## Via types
v1: diameter 20, hole 12, Top Layer to Bottom Layer, tented both sides, 430 vias

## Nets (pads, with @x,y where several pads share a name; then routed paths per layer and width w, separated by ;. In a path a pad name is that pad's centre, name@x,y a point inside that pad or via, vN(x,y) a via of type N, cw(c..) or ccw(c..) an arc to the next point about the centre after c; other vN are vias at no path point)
3.3V: C4.1 C7.1 C8.1 C13.1 C14.1 C22.2 C33.2 Cali3.1 J2.1 J4.1 J27.26 L1.2 LED0.1 LED1.1 Q1.2 R1.2 R5.2 R6.2 R8.1 R10.2 R11.2 R18.1 R19.1 S4.1 S4.4 U3.8 U5.5 U6.1 U6.24 | length 1397.2
  Top Layer w10: C8.1@730.66,3838.04 756.36,3812.34 834,3812.34 R10.2@860.84,3839.18 ; R10.2@856.31,3839.18 856.31,3916.18 ; U6.1@1959.98,3357.98 1959.98,3369.32 1983,3392.34 ; R11.2@2141.6,3153.42 v1(2141.6,3178) ; v1(2206.9,3088.05) R18.1@2206.9,3112.62 ; R1.2@2714.5,3869.82 2714.5,3862.5 2749.66,3827.34 2862.99,3827.34 Q1.2@2901.49,3865.84
  Top Layer w12: LED0.1@1970.63,3839.62 v1(2013.72,3839.62) ; v1(2167.62,3839.62) LED1.1@2210.71,3839.62 ; R6.2@2637.72,3539.34 v1(2637.72,3576.62) ; v1(2694.65,3576.62) 2706.72,3564.56 R5.2@2706.72,3539.34
  Top Layer w15: v1(1648,3542.53) R19.1@1667,3542.53 ; R8.1@1843,3053.37 v1(1864,3032.37) ; U6.24@1964,3160 1974,3160 v1(2010,3124) C14.1@2010,3094.49
  Top Layer w20: v1(901,3901.37) 923.56,3878.81 Cali3.1@958.81,3878.81 ; 1983,3392.34 v1(2006,3392.34) C13.1@2035,3392.34 ; 2022,3393.25 v1(2044,3415.25) 2065.09,3436.34 C33.2@2065.09,3448.34 ; S4.1@2161.34,2322.09 v1(2161.34,2393.66) ; v1(2161.34,2599) S4.4@2161.34,2672.09 ; U5.5@2196.69,3337.02 U5.5@2196.69,3349.02 ; U5.5@2196.69,3360.02 v1(2196.69,3407.34) 2196.69,3428.62 C22.2@2203.09,3435.02 ; v1(2713.63,3116) U3.8@2713.63,3166.06
  Top Layer w30: Q1.2@2901.49,3865.84 v1(2937,3865.84) v1(2961,3865.84)
  Bottom Layer w20: J4.1@3142.38,2817.72 J4.1@3148.82,2817.72 J4.1@3151,2815.54
  other v1: 901,3934.19
3.3V_6219: C5.1 C16.1 C17.1 C26.1 C28.2 C30.1 C34.2 C37.1 C38.1 Cali4.1 J35.3 R21.1 R23.1 U1.5 U6.5 U7.1 U11.8 | length 2967.6
  Top Layer w9.8: 1842.83,3429.31 1881.24,3390.9 U6.5@1881.24,3357.98
  Top Layer w12: C16.1@1812.01,3429.31 1842.83,3429.31
  Top Layer w15: 757.85,3308.15 770.96,3295.04 801.96,3295.04 829.37,3267.63 C38.1@829.37,3263.08 ; v1(757.85,3433.39) 788.93,3433.39 R23.1@789.37,3432.96 ; C37.1@829.37,3208.27 C37.1@829.37,3209.27 C38.1@829.37,3263.08 ; U11.8@929.85,3271.08 841.76,3271.08 833.76,3263.08 C38.1@829.37,3263.08 ; R21.1@1746.7,3471.65 1769.67,3471.65 C16.1@1812.01,3429.31
  Top Layer w20: U7.1@653.97,3329.3 653.97,3357.4 636.57,3374.8 C30.1@636.57,3379.39 636.57,3384.94 646.57,3394.94 C28.2@646.57,3433.39 v1(734,3433.39) ; 757.85,3308.15 757.85,3409.54 ; 1476,3485 C34.2@1623,3485 ; C34.2@1632,3485 1675.65,3485 C17.1@1689,3471.65 R21.1@1746.7,3471.65 ; v1(734,3433.39) 757.85,3409.54 ; v1(734,3433.39) v1(757.85,3433.39) 757.85,3409.54
  Top Layer w25: 1457,3485 1478,3506 ; 1478,3487 1478,3506 ; J35.3@1739.37,4169.09 1739.37,4164.71 1478,3903.34 1478,3506
  Top Layer w30: C26.1@952.59,3627.2 1081.8,3627.2 Cali4.1@1082,3627 1175.37,3627 1317.37,3485 1457,3485 1476,3485
  Bottom Layer w25: v1(734,3433.39) v1(757.85,3433.39) 888.39,3433.39 Cali4.1@1082,3627
5V: C1.1 C2.1 Cali1.1 J1.1 J4.2 J35.1 L2.2 R7.1 R9.2 U2.1 U2.4 | length 4960.3
  Top Layer w10: R9.2@409,4036.37 470.66,4036.37 477,4042.71 ; 477,3929.71 575,3929.71 601.93,3902.78 U2.1@657.81,3902.78
  Top Layer w30: L2.2@477,3741.9 477,3929.71 477,3996 ; 477,4042.71 477,3996 ; 512,3996 477,3996 ; J4.2@3048.82,2817.72 3048.82,2807.07 3099.55,2756.34 3193,2756.34 3226,2789.34 3226,3816.05 v1(3152.36,3889.69) v1(3134.71,3907.34)
  Bottom Layer w30: v1@489,4064.37 1205.97,4064.37 1308,3962.34 1732.61,3962.34 J35.1@1739.37,3969.09 1801.12,3907.34 v1(3134.71,3907.34) v1(3152.36,3889.69) ; R7.1@2850.63,2924.09 2957.01,2817.72 J4.2@3048.82,2817.72
  other v1: 489,4064.72 512,4064.72
5V/3.3VA_MICROP: J27.27 J35.2 | length 474
  Top Layer w25: J27.27@1541.98,3679.79 1541.98,3876.69 1734.38,4069.09 J35.2@1739.37,4069.09
ADC0/IO19_MICROP: J4.6 J27.17 U6.9 | length 3484.5
  Top Layer w6: v1(1779,3051) 1779.39,3051 1884.41,2945.99 2316.65,2945.99 2402.76,3032.09 2474.76,3032.09 2499.02,3056.36 2499.02,3522.75 J27.17@2441.98,3579.79
  Top Layer w8: v1(1767,3338) 1773.59,3331.41 U6.9@1795.61,3331.41
  Bottom Layer w6: J27.17@2441.98,3579.79 2469.43,3552.34 2914.61,3552.34 3022.22,3659.95 3175.51,3659.95 3198.71,3636.75 3198.71,3487.15 3171.41,3459.85 3127.61,3459.85 3105.31,3437.55 3105.31,3393.75 3125.61,3373.45 3186.01,3373.45 3229,3330.46 3229,3028.34 3174,2973.34 3093.2,2973.34 J4.6@3048.82,3017.72
  Bottom Layer w10: v1(1767,3338) 1778,3327 1778,3052.99 1779.99,3051 v1@1779.7,3051 ; v1(1779,3051) v1@1779.7,3051 ; v1@1780,3050.7 v1@1779.7,3051
ADC1/IO20_MICROP: J4.5 J27.16 U6.8 | length 2769.3
  Top Layer w6: v1(1807,3051.01) 1807,3043.69 1890.35,2960.34 2310.7,2960.34 2394.46,3044.09 2466.76,3044.09 2484,3061.34 2484,3437.77 J27.16@2441.98,3479.79 ; U6.8@1822.19,3357.98 U6.8@1822.19,3368.15
  Top Layer w8: v1(1799.35,3357.98) U6.8@1822.19,3357.98
  Bottom Layer w6: J27.16@2446.43,3475.34 J27.16@2441.98,3479.79 2469.52,3507.34 2985.33,3507.34 3026.52,3466.15 3066.01,3466.15 3092.31,3439.85 3092.31,3385.35 3118.81,3358.85 3176.97,3358.85 3214,3321.82 3214,3082.9 J4.5@3148.82,3017.72
  Bottom Layer w10: v1(1799.35,3357.98) 1799.35,3058.65 v1(1807,3051.01)
ADC1_0: J15.1 R14.1 | length 1072.6
  Top Layer w10: J15.1@1123.62,2409.45 1290,2575.83 1290,3041 1510.68,3261.68 R14.1@1570.69,3261.68
ADC1_1: J15.2 R17.1 | length 923.3
  Top Layer w10: J15.2@1322.01,2409.45 1322.01,3026.01 1462.18,3166.18 R17.1@1570.69,3166.18
ADC1_2: J12.2 J25.1 J25.5 R27.1 | length 1902.5
  Top Layer w10: J25.1@99,3096 109,3096 149,3056 149,2946 102.5,2899.5 158,2844 434,2844 557,2967 729,2967 746,2950 867.76,2950 J12.2@917.52,2900.24 ; v1(1547.39,3118.43) R27.1@1570.69,3118.43
  Bottom Layer w10: J12.2@917.52,2900.24 967.28,2950 1054,2950 1171,3067 1495.96,3067 v1(1547.39,3118.43)
ADC1_3: J5.2 J25.3 R28.1 | length 1806.6
  Top Layer w10: v1(1513.05,3119.48) 1515.06,3119.48 R28.1@1564.15,3070.39 ; R28.1@1565.95,3070.39 R28.1@1570.69,3070.39
  Bottom Layer w10: J25.3@99,2996 147.09,3044.09 358.09,3044.09 396,3082 396,3219.32 452.68,3276 654,3276 769,3161 865,3161 917.52,3108.48 J5.2@917.52,3100.24 978.28,3161 1122,3161 1154,3129 1503.53,3129 v1(1513.05,3119.48)
ADC1_4: J17.2 R29.1 | length 725.3
  Top Layer w10: v1(1490.36,3098.36) 1566.39,3022.34 R29.1@1570.69,3022.34
  Bottom Layer w10: J17.2@917.52,3000.24 967.04,3049.76 1109.81,3049.76 1158.41,3098.36 v1(1490.36,3098.36)
AGND: BZ1.2 C1.2 C2.2 C3.2 C4.2 C5.2 C6.2 C7.2 C9.2 C11.2 C12.2 C13.2 C14.2 C15.2 C16.2 C17.2 C18.1 C19.2 C20.2 C21.2 C22.1 C23.2 C24.2 C25.1 C26.2 C28.1 C29.1 C30.2 C31.2 C32.2 C33.1 C34.1 C35.1 C36.2 C37.2 C38.2 C40.1 C41.1 C42.1 C43.2 Cali2.1 Cali5.1 Cali9.1 D1.1 J1.5 J1.6 J1.7 J1.8 J1.9 J2.5 J4.3 J4.4 J26.1 J27.1 LED3.2 R12.1 R13.1 R26.2 R31.1 R33.2 R44.2 R49.1 RV2.1 S1.1 S1.4 S2.1 S2.4 U1.2 U2.2 U3.4 U3.5 U3.6 U3.7 U5.2 U6.6 U6.12 U6.33 U7.3 U11.4 X1.2 X1.4 | length 17445.8
  Top Layer w8: v1(1754.98,3272.35) U6.12@1795.61,3272.35
  Top Layer w9.8: v1(1849,3395) 1849,3393.88 1861.56,3381.32 U6.6@1861.56,3357.98
  Top Layer w10: v1(1649.52,3213.93) C9.2@1673.09,3213.93 ; v1(1649.52,3261.68) C25.1@1673.09,3261.68 ; v1(1650.52,3166.18) C11.2@1674.09,3166.18 ; 1650.68,3022.34 C32.2@1674.24,3022.34 C32.2@1674.24,3022.18 ; v1(1650.68,3070.68) C24.2@1674.24,3070.68 ; v1(1650.68,3118.43) C12.2@1674.24,3118.43 ; 1797.08,2929.34 2323.1,2929.34 2411.1,3017.34 2492,3017.34 2516,3041.34 v1@2516,3644.34 ; 1874,3609.33 1875.33,3609.33 1880.72,3603.94 2037.14,3603.94 2053.72,3587.35 v1(2053.72,3546.34)
  Top Layer w12: v1(789.72,3366.62) R31.1@789.72,3390.09
  Top Layer w15: J1.5@209.06,3984.25 J1.5@226,3984.25 ; v1(281,3984.25) J1.5@243,3984.25 ; v1(442,3007.37) C41.1@470,3007.37 ; v1(570.02,3379.39) C30.2@596.57,3379.39 ; v1(581,3244.3) U7.3@616.57,3244.3 v1(649.17,3244.3) ; R44.2@1172,3001.49 1172,2996 1181,2987 v1(1181,2968.27) ; C36.2@1218.94,3313.27 v1(1249.53,3313.27) ; v1(1746,3542.53) C23.2@1761,3542.53 ; v1(1790,3491) C16.2@1809.35,3471.65 ; v1(2501,4051.84) 2528,4024.84 v1(2528,3967.34) 2528,3906.34 v1(2631,3803.34) 2730,3704.34 2907.55,3704.34 v1(2915,3696.89) 2981.49,3630.4 2981.49,3538.5 2992,3527.99 ; J1.5@226,3984.25 226,3942 v1(243,3942) J1.5@243,3984.25 ; J1.5@226,3984.25 J1.5@243,3984.25
  Top Layer w20: v1(445.79,3226) C31.2@467.16,3247.37 467.16,3253.72 457.16,3263.72 C29.1@457.16,3308.46 454.85,3310.77 v1(454.85,3352.19) ; C40.1@510,3126.37 v1(546,3126.37) R33.2@586.57,3126.37 ; RV2.1@552.57,2751.71 v1(552.57,2817.71) C35.1@586.57,2851.71 ; v1(615.27,3940.18) U2.2@657.81,3940.18 v1(702,3940.18) v1@704,3940.18 ; v1(698,3548) 698,3566.95 v1(732.12,3601.07) U1.2@765,3601.07 ; C37.2@789.37,3208.27 C37.2@789.37,3209.27 C38.2@789.37,3263.08 ; R49.1@1228.94,3432.96 1230.69,3434.71 v1(1267.83,3434.71) ; v1(1509.88,3784.34) v1(1509.88,3854.34) 1509.88,3889.96 v1(1541.26,3921.34) v1(1628,4008.08) v1(1673.99,4054.07) ; v1(1592.41,3794.93) 1592.41,3602.93 1608,3587.34 ; C34.1@1631,3424 C34.1@1632,3425 1637.4,3425 1644.05,3431.65 v1(1666.53,3431.65) C17.2@1689,3431.65 ; v1(1649,3370.3) C20.2@1687.49,3370.3 C17.2@1687.49,3424 ; 1711,4258.34 v1(1746.34,4258.34) v1(1984.44,4258.34) 2186.5,4258.34 ; v1(1888.12,3750.34) 1893,3745.46 1893,3627 1875.33,3609.33 v1(1864,3598) v1(1864,3565.7) ; C18.1@1893.09,3438.92 v1(1864,3468) v1(1864,3518) v1(1864,3565.7) ; X1.2@1913.09,3565.7 v1(1864,3565.7) ; C19.2@2017.73,3438.92 v1(2017.73,3461.34) X1.4@2017.73,3480.74 ; v1(2051,3360.34) 2075,3384.34 C13.2@2075,3392.34 ; v1(2053.72,3546.34) 2053.72,3544.85 2065.09,3533.48 C33.1@2065.09,3508.34 ; v1(2121,3592.65) 2121,3624 2092,3653 v1(2092,3741.34) v1(2193,3741.34) 2193,3603.34 v1(2162,3572.34) ; C22.1@2203.09,3475.02 R12.1@2260,3475.02 v1(2260,3572.34) ; v1(2234.09,3203.34) U5.2@2234.09,3239.02 ; v1(2494,3818.34) v1(2533,3779.34) 2722,3590.34 v1(2744,3590.34) v1(2789,3590.34) ; v1(2563.63,3112.83) U3.5@2563.63,3166.06 ; U3.4@2563.63,3382.13 v1(2563.63,3433.34) v1(2563.63,3615.71) ; D1.1@2862.59,4022.84 3043.78,4022.84 BZ1.2@3090.55,3976.06 ; 2992,3527.99 v1(2992,3388.34) v1(2992,3296.34) v1(2992,3259.34) v1(2992,3138.34) 2992,2974.54 J4.4@3048.82,2917.72
  Top Layer w30: 935.35,3511.7 v1(1023,3511.7) v1@1136.86,3511.7
  Top Layer w35: J1.9@76,3893.02 v1@322,3893.02 ; J1.8@84.65,4177.17 J1.6@221.26,4177.17 309.17,4177.17
  Bottom Layer w15: v1(518,3784.71) v1(1183.79,3784.71) v1(1370.16,3598.34) v1(1439,3598.34) v1(1517,3598.34) v1(1608,3598.34) v1(1679,3598.34) 1863.66,3598.34 v1(1864,3598) ; v1(1740.3,3375) v1(1740.3,3343.85) 1740.3,3315.7 1754.98,3301.02 v1(1754.98,3272.35)
  Bottom Layer w20: v1(499,2541) 502.02,2537.98 v1(660.02,2537.98) v1(777.02,2537.98) ; v1(592,2590) v1(709,2590) 803,2590 ; v1@1397.14,3546.02 v1(1516.96,3546.02) ; v1(1691,3741.34) v1(2092,3741.34) v1(2193,3741.34) 2270,3818.34 v1(2494,3818.34) ; 1941,3572.34 v1(2260,3572.34) 2331,3572.34 2388,3629.34 2479,3629.34 2492.63,3615.71 v1(2563.63,3615.71) ; 1992.11,2956 1992.11,2851.22 2092,2751.34 ; 1995.11,3360.34 v1(2051,3360.34) 2110,3360.34 2234,3236.34 2234,3124.34 v1(2299,3059.34) ; 2092,2907.34 2092,2751.34 ; 2234.09,3230.34 v1(2326,3230.34) 2347,3230.34 ; v1(2563.63,3112.83) 2546.12,3130.34 2383,3130.34 2347,3166.34 2347,3230.34 ; v1(2579,3481.83) 2971.51,3481.83 v1(2997.5,3455.84) ; v1(2992,3259.34) 2963,3230.34 2347,3230.34 ; 3051.06,2672.09 2171.24,2672.09 2092,2751.34
  Bottom Layer w30: BZ1.2@3090.55,3976.06 3268,3976.06 3268,2759.68
  Bottom Layer w40: v1(2558.5,2846.84) 2733,3021.34 2937,3021.34 3040.62,2917.72 J4.4@3048.82,2917.72 J4.3@3148.82,2917.72 3222.41,2917.72
  other v1: 43.49,2286.34 259.14,2286.34 474.79,2286.34 690.44,2286.34 906.1,2286.34 1153.05,2286.34 1368.7,2286.34 1584.35,2286.34 1800,2287.4 2282.75,2289.34 2448.19,2289.34 2650,2289.34 2825,2289.34 2961,2289.34 3135,2289.34 1947.94,2292.34 433,2376 3273,2397 401.86,2436.87 2629,2447.34 2451,2455.34 3129,2456.34 476.39,2463.3 2291,2466.34 1047.14,2475 1266.29,2475 561,2480 39.58,2481 1898.47,2483 2114,2491 219.12,2515 843,2542 1698.13,2544 1470.65,2559.34 2451,2558.61 2928,2564.34 527,2573 377,2576.34 2610,2578.34 3052.09,2591.9 812,2599 927,2604.85 3274,2605 39.58,2621.97 2256,2628.34 1987.89,2641.34 398,2645 1746.15,2657.34 928.87,2672 3123.97,2672.09 188,2673 1236.34,2698.16 2282,2707.34 2450,2708.34 2880,2723 1009,2730 1869.77,2742.34 2107.5,2744.3 321,2745.6 2619,2745.6 3036.1,2751 1362.79,2758 39.58,2762.95 467.51,2771 1504.72,2786.34 188,2790.2 602.46,2799 2270,2806 2892,2806 1585,2811.34 2390,2821.34 2095,2823.34 1989,2825.34 3271.65,2830.06 1204,2835.49 2760,2865.56 1458,2876 359.02,2894 1262.5,2894 1127,2895 39.58,2903.92 2617,2906.34 454,2913 700,2923 1363.44,2943.34 2672.53,2958 2997,2959 2529,2960.34 1813.41,2968.27 1546,2969.34 1643,2969.34 1740,2969.34 2559,2984.34 2857,3002 667,3006.73 3271.65,3032.81 2611,3036.99 2206.9,3044.09 39.58,3044.9 767.52,3050.24 2119,3057 2101,3075.82 1746,3078 360,3085 2661,3100.54 1086,3125 761,3140 707.21,3145.11 2335,3153.02 2011.51,3168.99 1246.82,3170 1350.47,3173.49 370,3178 39.58,3185.87 160,3187 1517,3209 757.85,3210.08 875,3210.08 1840.09,3211.33 1891.09,3211.33 1942.09,3211.33 2143.11,3215 3271.65,3235.57 46,3250.83 1840.09,3262.51 1891.09,3262.51 1942.09,3262.51 1495,3280.68 1380,3283 2338,3295 217,3301.46 711,3304 417.39,3308.46 1840.09,3313.46 1891.09,3313.46 1942.09,3313.46 1033.16,3338.72 1462,3349.02 1767,3366 1585,3368.8 1526.37,3371.34 702,3387.37 873.29,3395.71 1409.33,3412 1295.28,3415.34 1527,3425.15 1584.98,3425.19 413.74,3430.49 2741.66,3432.79 545.67,3434.71 3271.65,3438.32 46,3453.58 574.9,3494 883.19,3503.37 745,3504.46 411.56,3506.34 618,3513 646,3513 1139.86,3514.71 532,3520 1210.96,3529.02 922.35,3529.77 1612,3543.2 1397.14,3546.34 216.55,3550.34 825,3553.19 1338,3553.91 473.04,3555.71 1080,3564.71 1147,3577.52 2562.89,3584.34 420,3594 2914,3595.34 833.79,3599.36 875.54,3599.92 420.14,3622.16 2681.93,3630.05 1258.97,3636 3271.65,3641.08 2964,3645.34 2516,3647.34 46,3656.34 820.35,3656.47 1133,3673.55 897,3684 1006.68,3692 1366,3692.69 1434,3692.69 2620,3692.69 515,3695.06 736.59,3695 854,3695 521.39,3740.37 775.63,3740.37 977.63,3740.37 1755.64,3743.34 2362.98,3777.34 369,3784 670.81,3785.55 979,3785.31 2813.26,3791.34 3098.82,3792.34 1983.37,3796.22 2150.71,3796.22 1757.47,3799.81 2949,3799.59 279,3804.34 51,3810.29 1841.87,3812.34 1659.61,3834.34 3271.65,3843.83 2273.82,3847 382.89,3859.96 1144.82,3860.96 511.09,3863.59 322,3892.34 1400.89,3896.3 1618,3896.83 1721.82,3900.81 704,3902.16 290,3947 208,3948.55 2371,3949.34 2644.52,3950.84 1200,3960.96 775,3961.76 1855,3961.76 602.46,3971.49 2168.16,3973.34 3173,3974.34 3015.03,3975.29 104.73,3978.25 2372,3986.34 2646,3988.34 1821,3994.79 734,4001 579.17,4012 612,4022.37 1541,4038.34 46,4039.34 300.8,4043.84 3271.65,4046.58 3172,4070.34 2635.61,4074.34 1452.49,4077.1 108.65,4090.88 621,4122 659,4122 977.63,4123.06 2897,4130.85 1263.09,4135 329,4164 562,4164.71 594.6,4164.71 1664.67,4167.98 385,4182 793,4202.37 2460.64,4249.34 2663.39,4249.34 2866.15,4249.34 3068.9,4249.34 3271.65,4249.34 39.58,4255.34 242.33,4255.34 360.5,4255.34 396.09,4255.34 494.48,4258.34 697.23,4258.34 899.98,4258.34 1102.74,4258.34 1305.49,4258.34 1508.25,4258.34 2222.54,4258.34
AVDD0: R21.2 U6.7 | length 135.4
  Top Layer w9.8: 1824.2,3390.84 1841.87,3373.16 U6.7@1841.87,3357.98
  Top Layer w15: R21.2@1746.7,3433.7 1753.69,3433.7 1796.55,3390.84 1824.2,3390.84
BEEP: J7.2 R2.1 | length 975.5
  Top Layer w6: R2.1@2715.69,3938.82 v1(2715.69,4016)
  Bottom Layer w6: J7.2@1839.37,4069.09 1892.46,4016 v1(2715.69,4016)
BOOT0: R26.1 S4.2 S4.3 U6.32 | length 1270
  Top Layer w6: U6.32@1986.56,3331.41 v1@2037.32,3331.41 ; v1(2037.32,3153.02) R26.1@2070,3153.02 ; S4.2@2341.34,2322.09 S4.3@2341.34,2672.09 v1(2341.34,2742.34)
  Bottom Layer w6: v1@2037.32,3331.41 v1(2037.32,3153.02) 2037.32,3058.75 2185,2911.06 2185,2811 2253.66,2742.34 v1(2341.34,2742.34)
  other v1: 2037.32,3333.41
CALI_0: C40.2 Cali6.1 J25.2 R32.1 R38.1 | length 416.3
  Top Layer w10: J25.2@180,3086.23 J25.2@180,3101 ; J25.2@199,3096 208.77,3086.23 Cali6.1@309.87,3086.23 350.02,3126.37 C40.2@470,3126.37 ; R38.1@470,3064 C40.2@470,3126.37 ; R32.1@470,3173.87 C40.2@470,3126.37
